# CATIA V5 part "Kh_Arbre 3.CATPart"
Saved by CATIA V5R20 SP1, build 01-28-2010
Part number: Arbre 3
Bounding box of the stored display mesh (mm): x -110 to 84, y -15 to 15, z -15 to 15
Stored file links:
  G:\Khaled_CFAO_2011\SIL\SIL_GR1\tmerino\Khaled\CAD_Thinkmotion\Kh_Arbre 3.CATPart
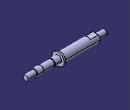
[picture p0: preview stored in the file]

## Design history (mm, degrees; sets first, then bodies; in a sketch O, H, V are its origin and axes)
Body1 (main body)
  Sketch1 on yz-plane, origin (0, 0, 0), H (0, 1, 0), V (0, 0, 1)
    circle A1 centre (0, 0) radius 15
    radius A1 = 15
  Pad1: profile Sketch1, direction (1, 0, 0), length 4
  Sketch2 on end face of Pad1, origin (4, 0, 0), H (0, 1, 0), V (0, 0, 1)
  Sketch3 on start face of Pad1, origin (0, 0, 0), H (0, -1, 0), V (0, 0, 1)
    circle A1 centre (0, 0) radius 11
    radius A1 = 11
  Pad2: profile Sketch3, direction (-1, 0, 0), length 88
  Sketch4 on end face of Pad2, origin (-88, 0, 0), H (0, -1, 0), V (0, 0, 1)
    circle A1 centre (0, 0) radius 6
    radius A1 = 6
  Pad3: profile Sketch4, direction (-1, 0, 0), length 22
  Sketch5 on zx-plane, origin (0, 0, 0), H (-1, 0, 0), V (0, 0, 1)
    line L1 (68, 20) -> (88, 20)
    line L2 (88, 20) -> (88, 8.5)
    line L3 (88, 8.5) -> (68, 8.5)
    line L4 (68, 8.5) -> (68, 20)
    reference projected line E1 (88, 11) -> (88, -11) from edge [face of Pad2 from Sketch3.A1 | end face of Pad2]
    reference projected line E2 through (0, 0) direction (1, 0) from axis of face of Pad2 from Sketch3.A1
    distance E1 L2 = 0
    distance L2 L4 = 20
    distance E2 L3 = 8.5
    horizontal: L1 H, L3 H
    vertical: L2 V, L4 V
  Pocket1: profile Sketch5, direction (0, 1, 0), length 22, opposite side length 22
  Sketch6 on end face of Pad1, origin (4, 0, 0), H (0, 1, 0), V (0, 0, 1)
    circle A1 centre (0, 0) radius 8.5
    radius A1 = 8.5
  Pad4: profile Sketch6, direction (1, 0, 0), length 16
  Sketch7 on end face of Pad4, origin (20, 0, 0), H (0, 1, 0), V (0, 0, 1)
    circle A1 centre (0, 0) radius 7.5
    radius A1 = 7.5
  Pad5: profile Sketch7, direction (1, 0, 0), length 26
  Sketch8 on end face of Pad5, origin (46, 0, 0), H (0, 1, 0), V (0, 0, 1)
    circle A1 centre (0, 0) radius 8.5
    radius A1 = 8.5
  Pad6: profile Sketch8, direction (1, 0, 0), length 16
  Sketch9 on end face of Pad6, origin (62, 0, 0), H (0, 1, 0), V (0, 0, 1)
    circle A1 centre (0, 0) radius 6
    radius A1 = 6
  Pad7: profile Sketch9, direction (1, 0, 0), length 22
  Chamfer1: length 1, angle 45, on edge [face of Pad4 from Sketch6.A1 | end face of Pad4]
  Chamfer2: length 1, angle 45, on edge [start face of Pad6 | face of Pad6 from Sketch8.A1]
  Fillet1: radius 2, on edge [start face of Pad1 | face of Pad2 from Sketch3.A1]
  Thread1: diameter 12, depth 10, pitch 1, on face of Pad3 from Sketch4.A1, from end face of Pad2
  Thread2: diameter 12, depth 10, pitch 1, on face of Pad7 from Sketch9.A1, from end face of Pad6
